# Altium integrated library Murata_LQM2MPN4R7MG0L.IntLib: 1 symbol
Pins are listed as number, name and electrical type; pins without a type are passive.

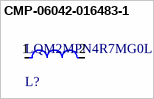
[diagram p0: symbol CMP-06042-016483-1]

## CMP-06042-016483-1
designator L?, comment LQM2MPN4R7MG0L
Multilayer Type Inductor for Power Lines, 0806 (2016), 4.7μH, 20%, 0.175Ω, 1.1A; Self Resonant Frequency: 20MHz; DC Resistance (DCR): 175mR; Test Frequency: 1MHz; Core Material: Ferrite; Shielding: Shielded; Inductance: 4.7uH
footprint FP-LQM2MPN_G0-IPC_B
footprint FP-LQM2MPN_G0-MFG
footprint FP-LQM2MPN_G0-IPC_A
footprint FP-LQM2MPN_G0-IPC_C
pins: 1, 2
